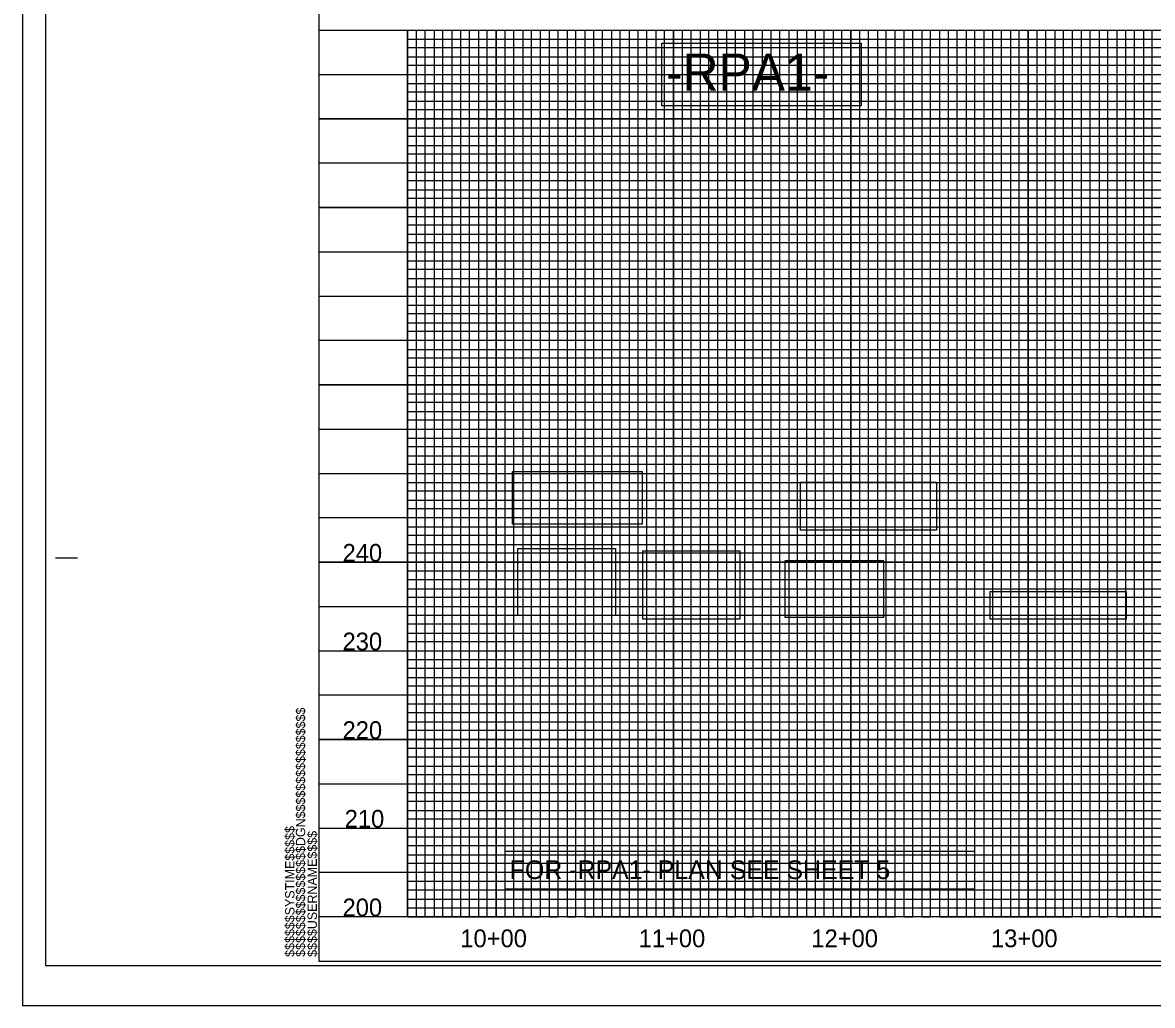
# Model space of a CAD drawing. Extents: x 1810963 to 1812908, y 722070 to 723170.
# Drawn here: x 1810963 to 1811601, y 722070 to 722624 of the extents above; entities that cross this region are included whole.
import ezdxf

# ---------------------------------------------------------------- set-up
doc = ezdxf.new("R2010")
doc.units = 0
for name, color, linetype in [('Exist Horizontal Alignment Tick Label', 7, 'Continuous'), ('Old_Level_11', 7, 'Continuous'), ('Old_Level_2', 7, 'Continuous'), ('Prop Conc 2ft 6in Curb and Gutter', 7, 'Continuous'), ('Prop PFL VPI Symbol CELL', 7, 'Continuous'), ('Prop RDY Traffic Signal CELL', 7, 'Continuous'), ('Prop Shade Heavy', 7, 'Continuous'), ('Prop Shade Light', 7, 'Continuous'), ('Scratch_Level_0', 7, 'Continuous'), ('Sheet Block Title CELL', 7, 'Continuous'), ('Sheet North Arrow CELL', 7, 'Continuous'), ('Sheet Symbology CELL', 7, 'Continuous'), ('Sheet Title CELL', 7, 'Continuous')]:
    doc.layers.add(name, color=color, linetype=linetype)

msp = doc.modelspace()

# ---------------------------------------------------------------- linework, layer by layer
at = {"layer": 'Old_Level_11'}
msp.add_lwpolyline([(1810976.46, 722092.33), (1812642.96, 722092.33), (1812642.96, 723147.43), (1810976.46, 723147.43)], close=True, dxfattribs=at)
at = {"layer": 'Old_Level_2'}
for points in [[(1811323.88, 722612.66), (1811436.27, 722612.66), (1811436.27, 722577.28), (1811323.88, 722577.28)], [(1811239.65, 722371.07), (1811312.91, 722371.07), (1811312.91, 722341.37), (1811239.65, 722341.37)], [(1811402.05, 722364.99), (1811478.82, 722364.99), (1811478.82, 722337.85), (1811402.05, 722337.85)], [(1811242.76, 722327.52), (1811297.72, 722327.52), (1811297.72, 722289.74), (1811242.76, 722289.74)], [(1811313.21, 722326.18), (1811367.95, 722326.18), (1811367.95, 722287.78), (1811313.21, 722287.78)], [(1811393.43, 722320.89), (1811449.01, 722320.89), (1811449.01, 722288.67), (1811393.43, 722288.67)], [(1811509.02, 722303.28), (1811585.78, 722303.28), (1811585.78, 722287.73), (1811509.02, 722287.73)], [(1811235.5, 722156.96), (1811500.18, 722156.96), (1811500.18, 722135.44), (1811235.5, 722135.44)]]:
    msp.add_lwpolyline(points, close=True, dxfattribs=at)
at = {"layer": 'Prop Conc 2ft 6in Curb and Gutter'}
for p, q in [((1811130.46, 722619.88), (1812630.35, 722619.88)), ((1811180.46, 722619.88), (1811180.46, 722119.88)), ((1811230.46, 722619.88), (1811230.46, 722119.88)), ((1811280.46, 722619.88), (1811280.46, 722119.88)), ((1811330.46, 722619.88), (1811330.46, 722119.88)), ((1811380.46, 722619.88), (1811380.46, 722119.88)), ((1811430.46, 722619.88), (1811430.46, 722119.88)), ((1811480.46, 722619.88), (1811480.46, 722119.88)), ((1811530.46, 722619.88), (1811530.46, 722119.88)), ((1811580.46, 722619.88), (1811580.46, 722119.88)), ((1811130.46, 722569.88), (1812630.35, 722569.88)), ((1811130.46, 722519.88), (1812630.35, 722519.88)), ((1811130.46, 722469.88), (1812630.35, 722469.88)), ((1811130.46, 722419.88), (1812630.35, 722419.88)), ((1811130.46, 722369.88), (1812630.35, 722369.88)), ((1811130.46, 722319.88), (1812630.35, 722319.88)), ((1811130.46, 722269.88), (1812630.35, 722269.88)), ((1811130.46, 722219.88), (1812630.35, 722219.88)), ((1811130.46, 722169.88), (1812630.35, 722169.88))]:
    msp.add_line(p, q, dxfattribs=at)
at = {"layer": 'Prop PFL VPI Symbol CELL'}
msp.add_lwpolyline([(1811180.46, 722619.88), (1812580.46, 722619.88), (1812580.46, 722119.88), (1811180.46, 722119.88)], close=True, dxfattribs=at)
at = {"layer": 'Prop RDY Traffic Signal CELL'}
for p, q in [((1810963.46, 723169.88), (1810963.46, 722069.88)), ((1810963.46, 722069.88), (1812647.46, 722069.88))]:
    msp.add_line(p, q, dxfattribs=at)
at = {"layer": 'Prop Shade Heavy'}
msp.add_line((1811130.46, 722119.88), (1811130.46, 722119.88), dxfattribs=at)
for points in [[(1811180.46, 722619.88), (1811180.46, 722119.88), (1811230.46, 722119.88), (1811230.46, 722619.88), (1811280.46, 722619.88), (1811280.46, 722119.88), (1811330.46, 722119.88), (1811330.46, 722619.88), (1811380.46, 722619.88), (1811380.46, 722119.88), (1811430.46, 722119.88), (1811430.46, 722619.88), (1811480.46, 722619.88), (1811480.46, 722119.88), (1811530.46, 722119.88), (1811530.46, 722619.88), (1811580.46, 722619.88), (1811580.46, 722119.88), (1811630.46, 722119.88)], [(1812630.46, 722569.88), (1811130.46, 722569.88)], [(1812630.46, 722519.88), (1811130.46, 722519.88), (1811130.46, 722469.88), (1812630.46, 722469.88)], [(1812630.46, 722419.88), (1811130.46, 722419.88), (1811130.46, 722369.88), (1812630.46, 722369.88)], [(1812630.46, 722319.88), (1811130.46, 722319.88), (1811130.46, 722269.88), (1812630.46, 722269.88)], [(1812630.46, 722219.88), (1811130.46, 722219.88), (1811130.46, 722219.88), (1811130.46, 722169.88), (1812630.46, 722169.88)], [(1812630.46, 722119.88), (1811130.46, 722119.88)]]:
    msp.add_lwpolyline(points, dxfattribs=at)
at = {"layer": 'Prop Shade Light'}
for points in [[(1811155.46, 722619.88), (1811205.46, 722619.88), (1811205.46, 722119.88), (1811255.46, 722119.88), (1811255.46, 722619.88), (1811305.46, 722619.88), (1811305.46, 722119.88), (1811355.46, 722119.88), (1811355.46, 722619.88), (1811405.46, 722619.88), (1811405.46, 722119.88), (1811455.46, 722119.88), (1811455.46, 722619.88), (1811505.46, 722619.88), (1811505.46, 722119.88), (1811555.46, 722119.88), (1811555.46, 722619.88), (1811605.46, 722619.88)], [(1811130.46, 722594.88), (1812630.46, 722594.88)], [(1812630.46, 722544.88), (1811130.46, 722544.88), (1811130.46, 722494.88), (1812630.46, 722494.88)], [(1812630.46, 722444.88), (1811130.46, 722444.88), (1811130.46, 722394.88), (1812630.46, 722394.88)], [(1812630.46, 722344.88), (1811130.46, 722344.88), (1811130.46, 722294.88), (1812630.46, 722294.88)], [(1812630.46, 722244.88), (1811130.46, 722244.88), (1811130.46, 722194.88), (1812630.46, 722194.88)], [(1812630.46, 722144.88), (1811130.46, 722144.88)]]:
    msp.add_lwpolyline(points, dxfattribs=at)
at = {"layer": 'Sheet North Arrow CELL'}
msp.add_lwpolyline([(1810963.46, 722069.88), (1812647.46, 722069.88), (1812647.46, 723169.88), (1810963.46, 723169.88)], close=True, dxfattribs=at)
at = {"layer": 'Sheet Symbology CELL'}
for p, q in [((1811130.46, 722619.88), (1812630.46, 722619.88)), ((1810981.96, 722322.38), (1810994.46, 722322.38)), ((1812630.46, 722119.88), (1811130.46, 722119.88)), ((1811130.46, 722094.88), (1812630.46, 722094.88)), ((1811130.46, 722094.88), (1811130.46, 722094.88)), ((1811130.46, 722094.88), (1811130.46, 722094.88)), ((1811130.46, 722094.88), (1811130.46, 722094.88)), ((1811130.46, 722094.88), (1811130.46, 722094.88)), ((1811130.46, 722094.88), (1811130.46, 722094.88)), ((1811130.46, 722094.88), (1811130.46, 722094.88)), ((1811130.46, 722094.88), (1811130.46, 722094.88))]:
    msp.add_line(p, q, dxfattribs=at)
msp.add_lwpolyline([(1812630.46, 723144.88), (1811130.46, 723144.88), (1811130.46, 722094.88), (1812630.46, 722094.88)], close=True, dxfattribs=at)
msp.add_lwpolyline([(1811160.99, 722094.88), (1811160.99, 722094.88)], dxfattribs=at)
at = {"layer": 'Sheet Title CELL'}
for p, q in [((1811180.46, 722614.88), (1812580.46, 722614.88)), ((1812580.46, 722609.88), (1811180.46, 722609.88)), ((1811180.46, 722604.88), (1812580.46, 722604.88)), ((1812580.46, 722599.88), (1811180.46, 722599.88)), ((1811180.46, 722589.88), (1812580.46, 722589.88)), ((1812580.46, 722584.88), (1811180.46, 722584.88)), ((1811180.46, 722579.88), (1812580.46, 722579.88)), ((1812580.46, 722574.88), (1811180.46, 722574.88)), ((1811180.46, 722564.88), (1812580.46, 722564.88)), ((1812580.46, 722559.88), (1811180.46, 722559.88)), ((1811180.46, 722554.88), (1812580.46, 722554.88)), ((1812580.46, 722549.88), (1811180.46, 722549.88)), ((1811180.46, 722539.88), (1812580.46, 722539.88)), ((1812580.46, 722534.88), (1811180.46, 722534.88)), ((1811180.46, 722529.88), (1812580.46, 722529.88)), ((1812580.46, 722524.88), (1811180.46, 722524.88)), ((1811180.46, 722514.88), (1812580.46, 722514.88)), ((1812580.46, 722509.88), (1811180.46, 722509.88)), ((1811180.46, 722504.88), (1812580.46, 722504.88)), ((1812580.46, 722499.88), (1811180.46, 722499.88)), ((1811180.46, 722489.88), (1812580.46, 722489.88)), ((1812580.46, 722484.88), (1811180.46, 722484.88)), ((1811180.46, 722479.88), (1812580.46, 722479.88)), ((1812580.46, 722474.88), (1811180.46, 722474.88)), ((1811180.46, 722464.88), (1812580.46, 722464.88)), ((1812580.46, 722459.88), (1811180.46, 722459.88)), ((1811180.46, 722454.88), (1812580.46, 722454.88)), ((1812580.46, 722449.88), (1811180.46, 722449.88)), ((1811180.46, 722439.88), (1812580.46, 722439.88)), ((1812580.46, 722434.88), (1811180.46, 722434.88)), ((1811180.46, 722429.88), (1812580.46, 722429.88)), ((1812580.46, 722424.88), (1811180.46, 722425.03)), ((1811180.46, 722414.88), (1812580.46, 722414.88)), ((1812580.46, 722409.88), (1811180.46, 722409.88)), ((1811180.46, 722404.88), (1812580.46, 722404.88)), ((1812580.46, 722399.88), (1811180.46, 722399.88)), ((1811180.46, 722389.88), (1812580.46, 722389.88)), ((1812580.46, 722384.88), (1811180.46, 722384.88)), ((1811180.46, 722379.88), (1812580.46, 722379.88)), ((1812580.46, 722374.88), (1811180.46, 722374.88)), ((1811180.46, 722364.88), (1812580.46, 722364.88)), ((1812580.46, 722359.88), (1811180.46, 722359.88)), ((1811180.46, 722354.88), (1812580.46, 722354.88)), ((1812580.46, 722349.88), (1811180.46, 722349.88)), ((1811180.46, 722339.88), (1812580.46, 722339.88)), ((1812580.46, 722334.88), (1811180.46, 722334.88)), ((1811180.46, 722329.88), (1812580.46, 722329.88)), ((1812580.46, 722324.88), (1811180.46, 722324.88)), ((1811180.46, 722314.88), (1812580.46, 722314.88)), ((1812580.46, 722309.88), (1811180.46, 722309.88)), ((1811180.46, 722304.88), (1812580.46, 722304.88)), ((1812580.46, 722299.88), (1811180.46, 722299.88)), ((1811180.46, 722289.88), (1812580.46, 722289.88)), ((1812580.46, 722284.88), (1811180.46, 722284.88)), ((1811180.46, 722279.88), (1812580.46, 722279.88)), ((1812580.46, 722274.88), (1811180.46, 722274.88)), ((1811180.46, 722264.88), (1812580.46, 722264.88)), ((1812580.46, 722259.88), (1811180.46, 722259.88)), ((1811180.46, 722254.88), (1812580.46, 722254.88)), ((1812580.46, 722249.88), (1811180.46, 722249.88)), ((1811180.46, 722239.88), (1812580.46, 722239.88)), ((1812580.46, 722234.88), (1811180.46, 722234.88)), ((1811180.46, 722229.88), (1812580.46, 722229.88)), ((1812580.46, 722224.88), (1811180.46, 722224.88)), ((1811180.46, 722214.88), (1812580.46, 722214.88)), ((1812580.46, 722209.88), (1811180.46, 722209.88)), ((1811180.46, 722204.88), (1812580.46, 722204.88)), ((1812580.46, 722199.88), (1811180.46, 722199.88)), ((1811180.46, 722189.88), (1812580.46, 722189.88)), ((1812580.46, 722184.88), (1811180.46, 722184.88)), ((1811180.46, 722179.88), (1812580.46, 722179.88)), ((1812580.46, 722174.88), (1811180.46, 722174.88)), ((1811180.46, 722164.88), (1812580.46, 722164.88)), ((1812580.46, 722159.88), (1811180.46, 722159.88)), ((1811180.46, 722154.88), (1812580.46, 722154.88)), ((1812580.46, 722149.88), (1811180.46, 722149.88)), ((1811180.46, 722139.88), (1812580.46, 722139.88)), ((1812580.46, 722134.88), (1811180.46, 722134.88)), ((1811180.46, 722129.88), (1812580.46, 722129.88)), ((1811180.46, 722124.88), (1812580.46, 722124.88))]:
    msp.add_line(p, q, dxfattribs=at)
for points in [[(1811180.46, 722619.88), (1811185.46, 722619.88), (1811185.46, 722119.88), (1811190.46, 722119.88), (1811190.46, 722619.88), (1811195.46, 722619.88), (1811195.46, 722119.88), (1811200.46, 722119.88), (1811200.46, 722619.88), (1811210.46, 722619.88), (1811210.46, 722119.88), (1811215.46, 722119.88), (1811215.46, 722619.88), (1811220.46, 722619.88), (1811220.46, 722119.88), (1811225.46, 722119.88), (1811235.46, 722119.88), (1811240.46, 722119.88), (1811240.46, 722619.88), (1811245.46, 722619.88), (1811245.46, 722119.88), (1811250.46, 722119.88), (1811250.46, 722619.88), (1811260.46, 722619.88), (1811260.46, 722119.88), (1811265.46, 722119.88), (1811265.46, 722619.88), (1811270.46, 722619.88), (1811270.46, 722119.88), (1811275.46, 722119.88), (1811275.46, 722619.88), (1811285.46, 722619.88), (1811285.46, 722119.88), (1811290.46, 722119.88), (1811290.46, 722619.88), (1811295.46, 722619.88), (1811295.46, 722119.88), (1811300.46, 722119.88), (1811300.46, 722619.88), (1811310.46, 722619.88), (1811310.46, 722119.88), (1811315.46, 722119.88), (1811315.46, 722619.88), (1811320.46, 722619.88), (1811320.46, 722119.88), (1811325.46, 722119.88), (1811325.46, 722619.88), (1811335.46, 722619.88), (1811335.46, 722119.88), (1811340.46, 722119.88), (1811340.46, 722619.88), (1811345.46, 722619.88), (1811345.46, 722119.88), (1811350.46, 722119.88), (1811350.46, 722619.88), (1811360.46, 722619.88), (1811360.46, 722119.88), (1811365.46, 722119.88), (1811365.46, 722619.88), (1811370.46, 722619.88), (1811370.46, 722119.88), (1811375.46, 722119.88), (1811375.46, 722619.88), (1811385.46, 722619.88), (1811385.46, 722119.88), (1811390.46, 722119.88), (1811390.46, 722619.88), (1811395.46, 722619.88), (1811395.46, 722119.88)], [(1811225.46, 722119.88), (1811225.46, 722619.88), (1811235.46, 722619.88), (1811235.46, 722119.88)], [(1811395.46, 722119.88), (1811400.46, 722119.88), (1811400.46, 722619.88), (1811410.46, 722619.88), (1811410.46, 722119.88), (1811415.46, 722119.88), (1811415.46, 722619.88), (1811420.46, 722619.88), (1811420.46, 722119.88), (1811425.46, 722119.88), (1811425.46, 722619.88), (1811435.46, 722619.88), (1811435.46, 722119.88), (1811440.46, 722119.88), (1811440.46, 722619.88), (1811445.46, 722619.88), (1811445.46, 722119.88), (1811450.46, 722119.88), (1811450.46, 722619.88), (1811460.46, 722619.88), (1811460.46, 722119.88), (1811465.46, 722119.88), (1811465.46, 722619.88), (1811470.46, 722619.88), (1811470.46, 722119.88), (1811475.46, 722119.88), (1811475.46, 722619.88), (1811485.46, 722619.88), (1811485.46, 722119.88), (1811490.46, 722119.88), (1811490.46, 722619.88), (1811495.46, 722619.88), (1811495.46, 722119.88), (1811500.46, 722119.88), (1811500.46, 722619.88), (1811510.46, 722619.88), (1811510.46, 722119.88), (1811515.46, 722119.88), (1811515.46, 722619.88), (1811520.46, 722619.88), (1811520.46, 722119.88), (1811525.46, 722119.88), (1811525.46, 722619.88), (1811535.46, 722619.88), (1811535.46, 722119.88), (1811540.46, 722119.88), (1811540.46, 722619.88), (1811545.46, 722619.88), (1811545.46, 722119.88), (1811550.46, 722119.88), (1811550.46, 722619.88), (1811560.46, 722619.88), (1811560.46, 722119.88), (1811565.46, 722119.88), (1811565.46, 722619.88), (1811570.46, 722619.88), (1811570.46, 722119.88), (1811575.46, 722119.88), (1811575.46, 722619.88), (1811585.46, 722619.88), (1811585.46, 722119.88), (1811590.46, 722119.88), (1811590.46, 722619.88), (1811595.46, 722619.88), (1811595.46, 722119.88), (1811600.46, 722119.88), (1811600.46, 722619.88), (1811610.46, 722619.88)]]:
    msp.add_lwpolyline(points, dxfattribs=at)

# ---------------------------------------------------------------- texts
at = {"layer": 'Exist Horizontal Alignment Tick Label'}
for s, height, p in [('-RPA1-', 21, (1811326.31, 722585.71)), ('FOR -RPA1- PLAN SEE SHEET 5', 10.5, (1811238.16, 722141.15))]:
    msp.add_text(s, height=height, rotation=360, dxfattribs=at).set_placement(p)
at = {"layer": 'Scratch_Level_0'}
for s, p in [('240', (1811143.89, 722320.13)), ('230', (1811143.89, 722270.13)), ('220', (1811143.89, 722220.13)), ('210', (1811145.09, 722170.13)), ('200', (1811143.89, 722120.13))]:
    msp.add_text(s, height=10, dxfattribs=at).set_placement(p)
at = {"layer": 'Sheet Block Title CELL'}
for s, p in [('10+00', (1811210.3, 722102.7)), ('11+00', (1811310.86, 722102.7)), ('12+00', (1811408.25, 722102.7)), ('13+00', (1811509.55, 722102.7))]:
    msp.add_text(s, height=10, dxfattribs=at).set_placement(p)
at = {"layer": 'Sheet Symbology CELL'}
for s, p in [('$$$$$$$$$$$$$$$$DGN$$$$$$$$$$$$$$$$', (1811122.82, 722097.26)), ('$$$$$$SYSTIME$$$$$', (1811116.77, 722097.26)), ('$$$$USERNAME$$$$', (1811129.4, 722097.27))]:
    msp.add_text(s, height=5.25, rotation=90, dxfattribs=at).set_placement(p)

doc.saveas('drawing.dxf')
